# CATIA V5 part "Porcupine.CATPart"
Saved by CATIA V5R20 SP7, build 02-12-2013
Part number: Porcupine
Bounding box of the stored display mesh (mm): x -89.725 to 466.436, y -34.827 to 2.594, z 0 to 0
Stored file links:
  C:\Users\CAS-\Desktop\Exercise Files\Porcupine.CATPart
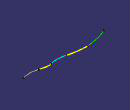
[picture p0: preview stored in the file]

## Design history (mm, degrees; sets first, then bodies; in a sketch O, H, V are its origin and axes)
AxisSystem1: origin (0, 0, 0), X (1, 0, 0), Y (0, 1, 0), Z (0, 0, 1)
Set1
  St3DCurveFeature1 "CATSt3DCurveFeatureName": Order 6, CreationType 1, ClosureMode false, ConstructionPoints ({point type Coord, X -89.725, Y -34.5072, Z 0}; {point type Coord, X -41.2492, Y -6.4085, Z 0}; {point type Coord, X 57.7845, Y 2.5939, Z 0}), SymmetryMode false
  St3DCurveFeature2 "CATSt3DCurveFeatureName": Order 6, CreationType 1, ClosureMode false, ConstructionPoints ({point type Coord, X 182.159, Y -14.5464, Z 0}; {point type Coord, X 240.3082, Y -31.2917, Z 0}; {point type Coord, X 288.6975, Y -17.0089, Z 0}), SymmetryMode false
  DatumCurve1
  Curve1: Elements the part
  Curve2: Elements the part
Body1 (main body)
